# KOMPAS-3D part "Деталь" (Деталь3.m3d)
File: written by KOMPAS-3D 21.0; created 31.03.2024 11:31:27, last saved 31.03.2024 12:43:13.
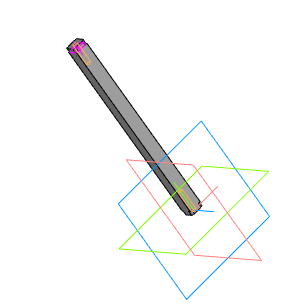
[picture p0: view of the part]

Document properties: Автор: Школа; Полное имя файла: C:\Users\Школа\Desktop\КУБСАТ ПРЕДПРОФФ\Ребро2.m3d

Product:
- Part/product: Деталь
    Масса: 0.02427
  - Body: Тело 1
      Масса: 0.023422

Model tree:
1. Эскиз:1
2. Элемент выдавливания:1
     Расстояние 1 = 2
3. Эскиз:2  (with: Элемент выдавливания:1)
4. Элемент выдавливания:2
     Расстояние 1 = 83
5. Эскиз:3  (with: Элемент выдавливания:2)
6. Элемент выдавливания:3
     Расстояние 1 = 2
7. Отверстие:1  (with: Элемент выдавливания:3)  (labels: M2)
     Глубина выреза = 10; Диаметр отверстия = 1.56699; Угол конуса дна = 118; Расстояние 1 = 3; Расстояние 2 = 3
8. M2  (with: Элемент выдавливания:3)  (labels: cil0_24705-2004 coarse)
     Длина резьбы = 10; Шаг резьбы = 0.4; Номинальный диаметр резьбы = 2
9. Отверстие:2  (with: Элемент выдавливания:1, M2)  (labels: M2; cil0_24705-2004 coarse)
     Глубина выреза = 10; Диаметр отверстия = 1.56699; Угол конуса дна = 118; Расстояние 1 = 3; Расстояние 2 = 3; Длина резьбы = 10; Шаг резьбы = 0.4; Номинальный диаметр резьбы = 2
